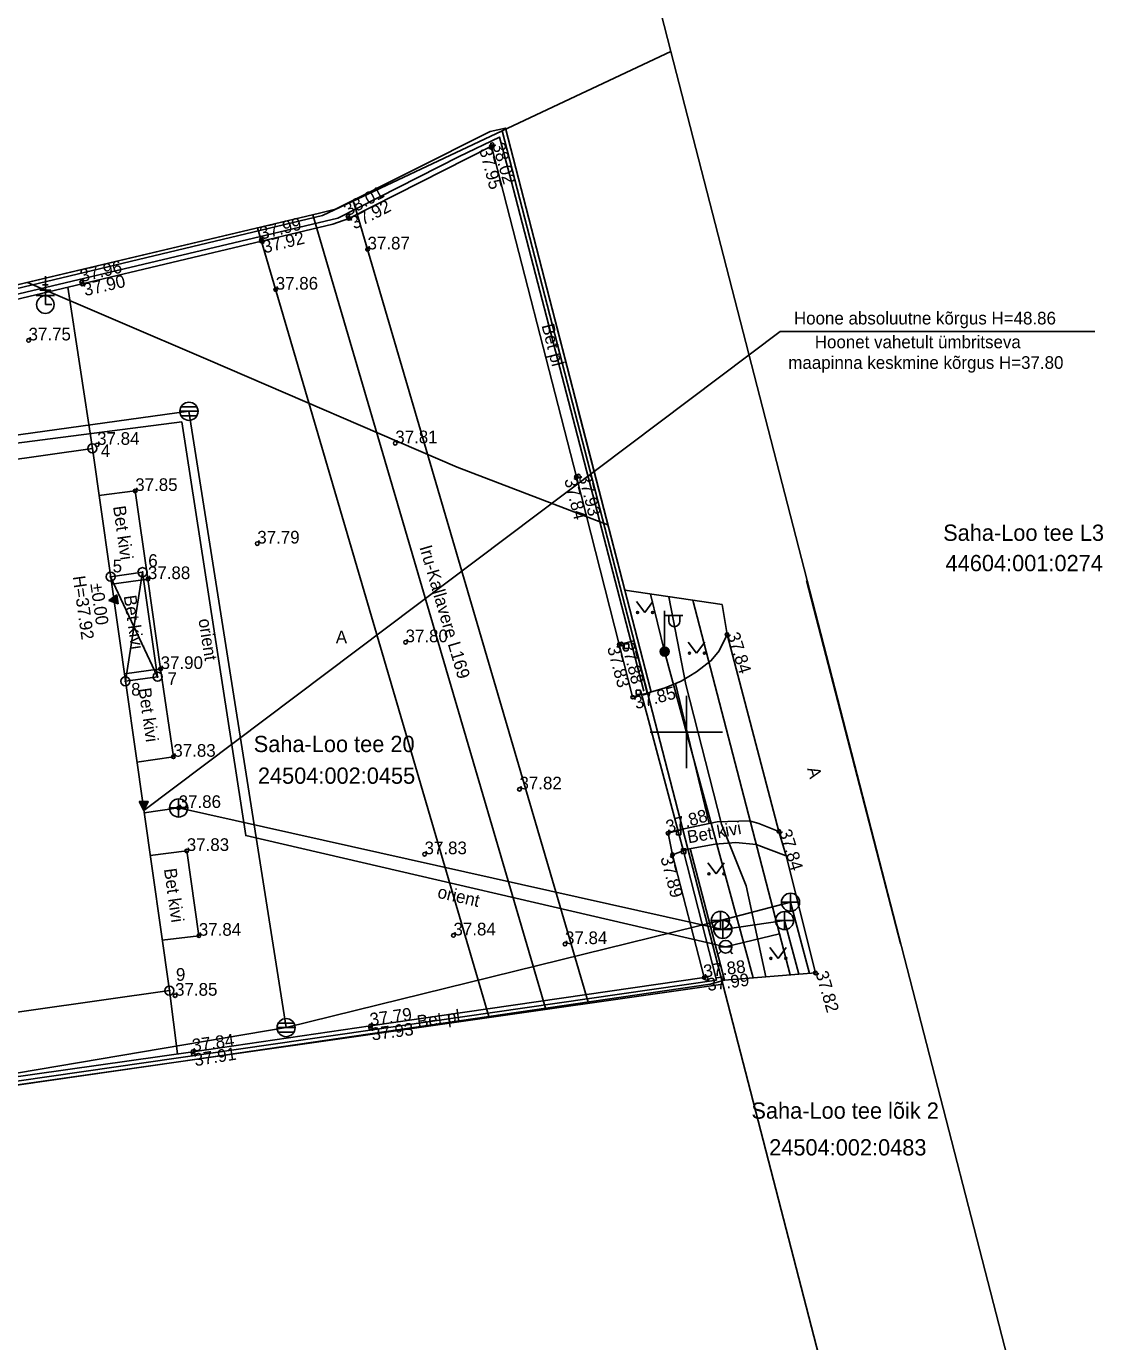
# Model space of a CAD drawing. Extents: x 551828 to 552309, y 6590593 to 6591152.
# Drawn here: x 552113.5 to 552174, y 6591016.3 to 6591089 of the extents above; entities that cross this region are included whole.
import ezdxf

# ---------------------------------------------------------------- set-up
doc = ezdxf.new("R2010")
doc.units = 0
for name, color, linetype in [('AED', 7, 'Continuous'), ('HALJASTUS', 7, 'Continuous'), ('HOONE', 7, 'Continuous'), ('HOONEDET', 7, 'Continuous'), ('KKAEV', 7, 'Continuous'), ('KOORDPUNKT', 7, 'Continuous'), ('KORGUS-EH2000', 7, 'Continuous'), ('KPOHULIIN', 7, 'Continuous'), ('KTRASS', 7, 'Continuous'), ('MOOTPIIR', 7, 'Continuous'), ('MPKAABEL', 7, 'Continuous'), ('PIIR', 7, 'Continuous'), ('POST', 7, 'Continuous'), ('PUU', 7, 'Continuous'), ('RAJATIS', 7, 'Continuous'), ('SITRASS', 7, 'Continuous'), ('SKKAEV', 7, 'Continuous'), ('SKTRASS', 7, 'Continuous'), ('TEE', 7, 'Continuous'), ('VKAEV', 7, 'Continuous'), ('VORK', 7, 'Continuous'), ('VTRASS', 7, 'Continuous')]:
    doc.layers.add(name, color=color, linetype=linetype)

msp = doc.modelspace()

# ---------------------------------------------------------------- linework, layer by layer
at = {"layer": 'AED'}
for p, q in [((552146.562, 6591054.882), (552146.562, 6591054.632)), ((552146.562, 6591054.882), (552146.812, 6591054.882)), ((552146.562, 6591054.632), (552146.812, 6591054.632)), ((552146.812, 6591054.882), (552146.812, 6591054.632)), ((552147.212, 6591052.328), (552147.212, 6591052.078)), ((552147.212, 6591052.328), (552147.462, 6591052.328)), ((552147.462, 6591052.328), (552147.462, 6591052.078)), ((552147.212, 6591052.078), (552147.462, 6591052.078)), ((552147.483, 6591052.25), (552149.566, 6591044.451)), ((552149.441, 6591044.576), (552149.441, 6591044.326)), ((552149.441, 6591044.576), (552149.691, 6591044.576)), ((552149.441, 6591044.326), (552149.691, 6591044.326)), ((552149.845, 6591043.418), (552149.566, 6591044.451)), ((552149.691, 6591044.576), (552149.691, 6591044.326)), ((552149.72, 6591043.543), (552149.72, 6591043.293)), ((552149.72, 6591043.543), (552149.97, 6591043.543)), ((552149.97, 6591043.543), (552149.97, 6591043.293)), ((552149.72, 6591043.293), (552149.97, 6591043.293))]:
    msp.add_line(p, q, dxfattribs=at)
for points in [[(552147.637, 6591052.26), (552140.304, 6591080.517), (552139.66, 6591082.912), (552137.43, 6591081.846), (552130.717, 6591078.419), (552116.026, 6591074.952), (552103.814, 6591072.044), (552061.896, 6591051.151)], [(552149.845, 6591043.418), (552151.659, 6591036.289), (552099.026, 6591028.695), (552056.657, 6591022.632), (552052.805, 6591046.621), (552057.329, 6591048.844)]]:
    msp.add_lwpolyline(points, dxfattribs=at)
msp.add_lwpolyline([(552146.282, 6591054.85), (552147.024, 6591051.953), (552147.828, 6591052.159), (552147.086, 6591055.056)], close=True, dxfattribs=at)
at = {"layer": 'HALJASTUS'}
for p, q in [((552147.238, 6591057.225), (552147.702, 6591056.618)), ((552147.702, 6591056.618), (552148.147, 6591057.225)), ((552150.1, 6591054.972), (552150.563, 6591054.366)), ((552150.563, 6591054.366), (552151.009, 6591054.972)), ((552151.184, 6591042.766), (552151.648, 6591042.159)), ((552151.648, 6591042.159), (552152.093, 6591042.766)), ((552154.609, 6591038.097), (552155.072, 6591037.49)), ((552155.072, 6591037.49), (552155.518, 6591038.097))]:
    msp.add_line(p, q, dxfattribs=at)
for centre in [(552147.301, 6591056.618), (552148.129, 6591056.618), (552150.162, 6591054.366), (552150.991, 6591054.366), (552151.247, 6591042.159), (552152.076, 6591042.159), (552154.671, 6591037.49), (552155.5, 6591037.49)]:
    msp.add_circle(centre, 0.055, dxfattribs=at)
at = {"layer": 'HOONE'}
msp.add_lwpolyline([(552071.587, 6591028.635), (552068.745, 6591048.736), (552098.36, 6591052.94), (552096.972, 6591062.824), (552117.134, 6591065.69), (552121.395, 6591035.706)], close=True, dxfattribs=at)
msp.add_lwpolyline([(552118.142, 6591058.596), (552119.91, 6591058.848), (552120.741, 6591053.064), (552118.964, 6591052.812)], dxfattribs=at)
at = {"layer": 'HOONEDET'}
for p, q in [((552118.964, 6591052.812), (552119.91, 6591058.848)), ((552118.142, 6591058.596), (552120.741, 6591053.064)), ((552118.039, 6591057.277), (552118.486, 6591057.589)), ((552118.189, 6591057.382), (552118.116, 6591057.251)), ((552118.236, 6591057.414), (552118.14, 6591057.242)), ((552118.283, 6591057.447), (552118.164, 6591057.234)), ((552118.33, 6591057.48), (552118.188, 6591057.226)), ((552118.377, 6591057.513), (552118.212, 6591057.218)), ((552118.424, 6591057.546), (552118.236, 6591057.21)), ((552118.471, 6591057.579), (552118.26, 6591057.201)), ((552118.49, 6591057.562), (552118.284, 6591057.193)), ((552118.496, 6591057.521), (552118.308, 6591057.185)), ((552118.502, 6591057.48), (552118.332, 6591057.177)), ((552118.507, 6591057.439), (552118.356, 6591057.169)), ((552118.513, 6591057.398), (552118.38, 6591057.161)), ((552118.519, 6591057.357), (552118.404, 6591057.152)), ((552118.555, 6591057.101), (552118.486, 6591057.589)), ((552118.039, 6591057.277), (552118.555, 6591057.101)), ((552118.048, 6591057.283), (552118.043, 6591057.275)), ((552118.095, 6591057.316), (552118.067, 6591057.267)), ((552118.142, 6591057.349), (552118.091, 6591057.259)), ((552118.525, 6591057.317), (552118.428, 6591057.144)), ((552118.531, 6591057.276), (552118.453, 6591057.136)), ((552118.536, 6591057.235), (552118.477, 6591057.128)), ((552118.542, 6591057.194), (552118.501, 6591057.12)), ((552118.548, 6591057.153), (552118.525, 6591057.112)), ((552118.554, 6591057.112), (552118.549, 6591057.103)), ((552119.979, 6591045.671), (552119.733, 6591046.158)), ((552120.225, 6591046.158), (552119.733, 6591046.158)), ((552119.741, 6591046.141), (552120.085, 6591045.88)), ((552119.76, 6591046.158), (552120.096, 6591045.902)), ((552119.767, 6591046.09), (552120.073, 6591045.857)), ((552119.793, 6591046.039), (552120.062, 6591045.834)), ((552119.802, 6591046.158), (552120.108, 6591045.925)), ((552119.819, 6591045.988), (552120.05, 6591045.812)), ((552119.843, 6591046.158), (552120.119, 6591045.948)), ((552119.844, 6591045.937), (552120.039, 6591045.789)), ((552119.87, 6591045.886), (552120.027, 6591045.766)), ((552119.884, 6591046.158), (552120.13, 6591045.97)), ((552119.896, 6591045.835), (552120.016, 6591045.744)), ((552119.922, 6591045.783), (552120.004, 6591045.721)), ((552119.925, 6591046.158), (552120.142, 6591045.993)), ((552119.948, 6591045.732), (552119.993, 6591045.698)), ((552119.967, 6591046.158), (552120.153, 6591046.016)), ((552119.979, 6591045.671), (552120.225, 6591046.158)), ((552120.008, 6591046.158), (552120.165, 6591046.038)), ((552120.049, 6591046.158), (552120.176, 6591046.061)), ((552120.09, 6591046.158), (552120.188, 6591046.084)), ((552120.132, 6591046.158), (552120.199, 6591046.106)), ((552120.173, 6591046.158), (552120.211, 6591046.129)), ((552120.214, 6591046.158), (552120.222, 6591046.152)), ((552119.974, 6591045.681), (552119.981, 6591045.675))]:
    msp.add_line(p, q, dxfattribs=at)
msp.add_lwpolyline([(552119.979, 6591045.671), (552155.19, 6591072.167), (552172.6, 6591072.167)], dxfattribs=at)
at = {"layer": 'KKAEV'}
for p, q in [((552121.409, 6591045.807), (552122.409, 6591045.807)), ((552121.909, 6591045.307), (552121.909, 6591046.307)), ((552155.427, 6591039.081), (552155.427, 6591040.081)), ((552152.013, 6591038.593), (552152.013, 6591039.593)), ((552154.927, 6591039.581), (552155.927, 6591039.581)), ((552151.513, 6591039.093), (552152.513, 6591039.093))]:
    msp.add_line(p, q, dxfattribs=at)
for centre in [(552121.909, 6591045.807), (552155.427, 6591039.581), (552152.013, 6591039.093)]:
    msp.add_circle(centre, 0.5, dxfattribs=at)
at = {"layer": 'KOORDPUNKT'}
for centre, radius in [((552117.134, 6591065.69), 0.25), ((552117.134, 6591065.69), 0.025), ((552117.134, 6591065.69), 0.0221), ((552117.134, 6591065.69), 0.0191), ((552117.134, 6591065.69), 0.0161), ((552117.134, 6591065.69), 0.0132), ((552117.134, 6591065.69), 0.0102), ((552117.134, 6591065.69), 0.00726), ((552117.134, 6591065.69), 0.0043), ((552118.142, 6591058.596), 0.25), ((552119.91, 6591058.848), 0.25), ((552119.91, 6591058.848), 0.025), ((552119.91, 6591058.848), 0.0221), ((552119.91, 6591058.848), 0.0191), ((552119.91, 6591058.848), 0.0161), ((552119.91, 6591058.848), 0.0132), ((552119.91, 6591058.848), 0.0102), ((552119.91, 6591058.848), 0.00726), ((552119.91, 6591058.848), 0.0043), ((552118.142, 6591058.596), 0.025), ((552118.142, 6591058.596), 0.0221), ((552118.142, 6591058.596), 0.0191), ((552118.142, 6591058.596), 0.0161), ((552118.142, 6591058.596), 0.0132), ((552118.142, 6591058.596), 0.0102), ((552118.142, 6591058.596), 0.00726), ((552118.142, 6591058.596), 0.0043), ((552118.964, 6591052.812), 0.25), ((552120.741, 6591053.064), 0.25), ((552120.741, 6591053.064), 0.025), ((552120.741, 6591053.064), 0.0221), ((552120.741, 6591053.064), 0.0191), ((552120.741, 6591053.064), 0.0161), ((552120.741, 6591053.064), 0.0132), ((552120.741, 6591053.064), 0.0102), ((552120.741, 6591053.064), 0.00726), ((552120.741, 6591053.064), 0.0043), ((552118.964, 6591052.812), 0.025), ((552118.964, 6591052.812), 0.0221), ((552118.964, 6591052.812), 0.0191), ((552118.964, 6591052.812), 0.0161), ((552118.964, 6591052.812), 0.0132), ((552118.964, 6591052.812), 0.0102), ((552118.964, 6591052.812), 0.00726), ((552118.964, 6591052.812), 0.0043), ((552121.395, 6591035.706), 0.25), ((552121.395, 6591035.706), 0.025), ((552121.395, 6591035.706), 0.0221), ((552121.395, 6591035.706), 0.0191), ((552121.395, 6591035.706), 0.0161), ((552121.395, 6591035.706), 0.0132), ((552121.395, 6591035.706), 0.0102), ((552121.395, 6591035.706), 0.00726), ((552121.395, 6591035.706), 0.0043)]:
    msp.add_circle(centre, radius, dxfattribs=at)
at = {"layer": 'KORGUS-EH2000'}
for centre in [(552139.21, 6591082.402), (552139.253, 6591082.496), (552131.28, 6591078.525), (552131.316, 6591078.414), (552126.486, 6591077.157), (552126.487, 6591077.237), (552132.358, 6591076.699), (552116.549, 6591074.89), (552116.575, 6591074.794), (552127.278, 6591074.476), (552113.605, 6591071.667), (552117.401, 6591065.892), (552133.891, 6591065.978), (552143.916, 6591064.13), (552144.029, 6591064.163), (552119.506, 6591063.34), (552126.258, 6591060.432), (552120.208, 6591058.466), (552152.244, 6591055.402), (552134.46, 6591054.973), (552146.282, 6591054.85), (552146.403, 6591054.869), (552120.911, 6591053.494), (552147.028, 6591051.936), (552121.615, 6591048.64), (552140.762, 6591046.836), (552121.909, 6591045.807), (552148.987, 6591044.41), (552155.116, 6591044.507), (552122.358, 6591043.432), (552135.511, 6591043.249), (552149.228, 6591043.224), (552123.026, 6591038.741), (552137.112, 6591038.758), (552143.28, 6591038.278), (552150.98, 6591036.429), (552151.096, 6591036.377), (552157.134, 6591036.685), (552121.712, 6591035.423), (552132.526, 6591033.639), (552132.528, 6591033.755), (552122.699, 6591032.327), (552122.714, 6591032.214)]:
    msp.add_circle(centre, 0.1, dxfattribs=at)
at = {"layer": 'KPOHULIIN'}
for p, q in [((552144.567, 6591035.072), (552131.562, 6591079.413)), ((552142.201, 6591034.727), (552129.329, 6591078.611)), ((552139.071, 6591034.269), (552126.277, 6591077.887))]:
    msp.add_line(p, q, dxfattribs=at)
at = {"layer": 'KTRASS'}
for p, q in [((552119.998, 6591045.535), (552121.909, 6591045.807)), ((552121.909, 6591045.807), (552152.013, 6591039.093)), ((552152.013, 6591039.093), (552155.427, 6591039.581)), ((552155.427, 6591039.581), (552156.209, 6591036.611))]:
    msp.add_line(p, q, dxfattribs=at)
at = {"layer": 'MOOTPIIR'}
msp.add_lwpolyline([(552103.559, 6591072.502), (552116.628, 6591075.6), (552129.697, 6591078.698), (552130.577, 6591078.919), (552139.137, 6591083.215), (552139.991, 6591083.412), (552144, 6591067.885), (552146.592, 6591057.845), (552151.974, 6591057.057), (552152.244, 6591055.402), (552155.116, 6591044.507), (552155.516, 6591043.166), (552157.134, 6591036.685), (552152.101, 6591036.283), (552151.303, 6591036.057), (552121.905, 6591031.76), (552098.767, 6591028.437)], dxfattribs=at)
at = {"layer": 'MPKAABEL'}
for points in [[(552148.01, 6591057.637), (552148.795, 6591054.459), (552153.686, 6591036.41)], [(552149.031, 6591057.488), (552149.964, 6591052.643), (552151.932, 6591044.904), (552153.302, 6591041.492), (552154.389, 6591036.466)]]:
    msp.add_lwpolyline(points, dxfattribs=at)
at = {"layer": 'PIIR'}
for points in [[(552143.71, 6591108.79), (552149.14, 6591087.65), (552174.83, 6590987.99), (552199.8, 6590891.16), (552215.43, 6590830.96), (552218.38, 6590819.63), (552233.09, 6590762.58), (552245.52, 6590714.43), (552247.96, 6590705.32), (552276.62, 6590593.49), (552283.18, 6590594.89), (552309.49, 6590600.56), (552291.06, 6590677.95), (552287.13, 6590694.59), (552278.69, 6590730.27), (552251.37, 6590840.7), (552224.32, 6590947.63), (552220.28, 6590964.73), (552176.02, 6591151.99)], [(552139.81, 6591083.25), (552152.01, 6591036.07), (552164.61, 6590987.36), (552178.47, 6590933.78), (552192.33, 6590880.2), (552205.44, 6590829.53), (552215.43, 6590830.96), (552199.8, 6590891.16), (552174.83, 6590987.99), (552149.14, 6591087.65)], [(552052.64, 6591046.67), (552056.49, 6591022.44), (552152.01, 6591036.07), (552139.81, 6591083.25), (552129.86, 6591078.57), (552103.56, 6591072.29)], [(552056.49, 6591022.44), (552064.25, 6590973.06), (552164.61, 6590987.36), (552152.01, 6591036.07)]]:
    msp.add_lwpolyline(points, close=True, dxfattribs=at)
msp.add_lwpolyline([(551994.68, 6591017.51), (552041.41, 6591041.02), (552052.64, 6591046.67), (552103.56, 6591072.29), (552129.86, 6591078.57), (552139.81, 6591083.25), (552149.14, 6591087.65), (552143.71, 6591108.79), (552138.17, 6591106.07), (552120.12, 6591097.22), (552089.7, 6591078.79), (552070.79, 6591069.29), (552053.16, 6591060.44), (552032.69, 6591050.15), (552014.5, 6591041)], dxfattribs=at)
at = {"layer": 'POST'}
for p, q in [((552148.795, 6591054.709), (552148.795, 6591056.709)), ((552148.795, 6591056.459), (552149.795, 6591056.459)), ((552149.022, 6591056.138), (552149.022, 6591056.459)), ((552149.635, 6591056.138), (552149.635, 6591056.459)), ((552148.795, 6591054.459), (552148.795, 6591054.459))]:
    msp.add_line(p, q, dxfattribs=at)
for radius in [0.25, 0.225, 0.2, 0.175, 0.15, 0.125, 0.1, 0.075, 0.05, 0.025]:
    msp.add_circle((552148.795, 6591054.459), radius, dxfattribs=at)
msp.add_arc((552149.328, 6591056.138), 0.306, 180, 0, dxfattribs=at)
at = {"layer": 'PUU'}
for p, q in [((552114.536, 6591073.647), (552114.536, 6591075.222)), ((552115.036, 6591074.147), (552114.036, 6591074.147)), ((552114.836, 6591074.447), (552114.236, 6591074.447)), ((552114.686, 6591074.747), (552114.386, 6591074.747)), ((552114.896, 6591073.647), (552114.536, 6591073.647))]:
    msp.add_line(p, q, dxfattribs=at)
at = {"layer": 'RAJATIS'}
msp.add_circle((552114.536, 6591073.647), 0.486, dxfattribs=at)
at = {"layer": 'SITRASS'}
msp.add_lwpolyline([(552113.542, 6591074.868), (552123.55, 6591070.6), (552137.32, 6591064.66), (552145.657, 6591061.464)], dxfattribs=at)
at = {"layer": 'SKKAEV'}
for p, q in [((552121.981, 6591067.745), (552122.981, 6591067.745)), ((552122.911, 6591067.995), (552122.051, 6591067.995)), ((552122.911, 6591067.495), (552122.051, 6591067.495)), ((552155.757, 6591040.093), (552155.757, 6591041.093)), ((552151.876, 6591039.084), (552151.876, 6591040.084)), ((552155.257, 6591040.593), (552156.257, 6591040.593)), ((552151.376, 6591039.584), (552152.376, 6591039.584)), ((552127.352, 6591033.656), (552128.352, 6591033.656)), ((552128.282, 6591033.906), (552127.422, 6591033.906)), ((552128.282, 6591033.406), (552127.422, 6591033.406))]:
    msp.add_line(p, q, dxfattribs=at)
for centre in [(552122.481, 6591067.745), (552155.757, 6591040.593), (552151.876, 6591039.584), (552127.852, 6591033.656)]:
    msp.add_circle(centre, 0.5, dxfattribs=at)
at = {"layer": 'SKTRASS'}
for p, q in [((552090.914, 6591063.376), (552122.481, 6591067.745)), ((552122.481, 6591067.745), (552127.852, 6591033.656)), ((552151.876, 6591039.584), (552155.757, 6591040.593)), ((552155.757, 6591040.593), (552156.816, 6591036.66)), ((552127.852, 6591033.656), (552151.876, 6591039.584)), ((552097.953, 6591028.627), (552127.852, 6591033.656))]:
    msp.add_line(p, q, dxfattribs=at)
at = {"layer": 'TEE'}
for p, q in [((552117.134, 6591065.69), (552115.783, 6591074.606)), ((552156.648, 6591058.387), (552161.845, 6591038.309)), ((552149.386, 6591052.689), (552151.256, 6591044.944)), ((552121.842, 6591032.206), (552121.395, 6591035.706))]:
    msp.add_line(p, q, dxfattribs=at)
for points in [[(552146.282, 6591054.85), (552147.086, 6591055.056), (552147.828, 6591052.159), (552148.048, 6591052.225), (552148.008, 6591052.359), (552139.991, 6591083.412), (552139.137, 6591083.215), (552130.577, 6591078.919), (552129.697, 6591078.698), (552103.559, 6591072.502), (552061.628, 6591051.575)], [(552103.896, 6591071.784), (552116.575, 6591074.794), (552126.486, 6591077.157), (552130.443, 6591078.094), (552131.316, 6591078.414), (552139.21, 6591082.402), (552143.916, 6591064.13), (552146.282, 6591054.85)], [(552117.502, 6591063.096), (552119.506, 6591063.34), (552120.208, 6591058.466), (552118.199, 6591058.191)], [(552120.208, 6591058.466), (552120.911, 6591053.494), (552118.905, 6591053.229)], [(552157.134, 6591036.685), (552155.516, 6591043.166), (552155.116, 6591044.507), (552152.244, 6591055.402), (552151.974, 6591057.057)], [(552147.828, 6591052.159), (552148.823, 6591052.458), (552149.705, 6591052.82), (552150.553, 6591053.329), (552151.373, 6591053.96), (552151.801, 6591054.504), (552152.244, 6591055.402)], [(552120.911, 6591053.494), (552121.615, 6591048.64), (552119.6, 6591048.336)], [(552057.2, 6591049.342), (552052.503, 6591047.042), (552054.752, 6591033.19), (552056.403, 6591023.066), (552056.51, 6591022.407), (552059.117, 6591022.785), (552070.742, 6591024.47), (552097.257, 6591028.201), (552097.324, 6591027.687), (552098.829, 6591027.951), (552098.767, 6591028.437), (552121.905, 6591031.76), (552151.303, 6591036.057), (552152.101, 6591036.283), (552150.21, 6591043.556)], [(552149.852, 6591044.656), (552151.702, 6591045.035), (552153.482, 6591045.092), (552154.011, 6591044.956), (552155.116, 6591044.507)], [(552149.852, 6591044.656), (552148.987, 6591044.41), (552149.228, 6591043.224), (552150.98, 6591036.429), (552132.528, 6591033.755), (552122.699, 6591032.327), (552098.285, 6591028.866)], [(552155.516, 6591043.166), (552153.863, 6591043.783), (552152.74, 6591043.899), (552151.586, 6591043.803), (552150.056, 6591043.528), (552149.228, 6591043.224)], [(552120.334, 6591043.176), (552122.358, 6591043.432), (552123.026, 6591038.741), (552120.999, 6591038.492)]]:
    msp.add_lwpolyline(points, dxfattribs=at)
at = {"layer": 'VKAEV'}
for p, q in [((552151.919, 6591037.887), (552151.779, 6591037.747)), ((552151.816, 6591038.134), (552152.516, 6591038.134)), ((552152.413, 6591037.887), (552152.553, 6591037.747))]:
    msp.add_line(p, q, dxfattribs=at)
msp.add_circle((552152.166, 6591038.134), 0.35, dxfattribs=at)
at = {"layer": 'VORK'}
for p, q in [((552150, 6591052), (552150, 6591048)), ((552148, 6591050), (552152, 6591050))]:
    msp.add_line(p, q, dxfattribs=at)
at = {"layer": 'VTRASS'}
msp.add_line((552152.166, 6591038.134), (552155.154, 6591038.852), dxfattribs=at)
for points in [[(552097.831, 6591062.946), (552098.934, 6591064.176), (552122.078, 6591067.157), (552125.621, 6591044.276), (552152.166, 6591038.134)], [(552150.351, 6591057.294), (552155.154, 6591038.852), (552155.74, 6591036.574)]]:
    msp.add_lwpolyline(points, dxfattribs=at)

# ---------------------------------------------------------------- texts
at = {"layer": 'HOONEDET'}
for s, p in [('Hoone absoluutne kõrgus H=48.86', (552155.947, 6591072.548)), ('Hoonet vahetult ümbritseva', (552157.101, 6591071.233)), ('maapinna keskmine kõrgus H=37.80', (552155.635, 6591070.094))]:
    msp.add_text(s, height=0.7, dxfattribs=at).set_placement(p)
for s, p in [('H=37.92', (552116.045, 6591058.603)), ('±0.00', (552117.022, 6591058.194))]:
    msp.add_text(s, height=0.7, rotation=278.0898, dxfattribs=at).set_placement(p)
at = {"layer": 'KOORDPUNKT'}
for s, p in [('4', (552117.607, 6591065.216)), ('5', (552118.26, 6591058.837)), ('6', (552120.227, 6591059.141)), ('7', (552121.295, 6591052.606)), ('8', (552119.28, 6591052.022)), ('9', (552121.759, 6591036.248))]:
    msp.add_text(s, height=0.7, dxfattribs=at).set_placement(p)
at = {"layer": 'KORGUS-EH2000'}
for s, rotation, p in [('37.95', 284.71435, (552138.533, 6591082.225)), ('38.02', 285.9746, (552139.253, 6591082.496)), ('38.01', 28.07902, (552131.28, 6591078.525)), ('37.92', 26.97686, (552131.634, 6591077.791)), ('37.99', 14.18851, (552126.487, 6591077.237)), ('37.92', 13.77406, (552126.653, 6591076.477)), ('37.96', 13.40771, (552116.549, 6591074.89)), ('37.90', 12.98004, (552116.732, 6591074.112)), ('37.84', 284.01176, (552143.237, 6591063.961)), ('37.93', 284.07847, (552144.029, 6591064.163)), ('37.84', 287.39927, (552152.244, 6591055.402)), ('37.83', 285.18118, (552145.606, 6591054.666)), ('37.88', 284.47422, (552146.403, 6591054.869)), ('37.85', 15.18664, (552147.212, 6591051.261)), ('37.88', 16.82995, (552148.987, 6591044.41)), ('37.84', 287.18076, (552155.116, 6591044.507)), ('37.89', 284.93272, (552148.552, 6591043.044)), ('37.88', 6.91199, (552150.98, 6591036.429)), ('37.99', 7.39723, (552151.186, 6591035.683)), ('37.82', 286.1649, (552157.134, 6591036.685)), ('37.79', 7.8724, (552132.528, 6591033.755)), ('37.93', 7.47348, (552132.617, 6591032.945)), ('37.84', 7.63735, (552122.699, 6591032.327)), ('37.91', 9.11334, (552122.825, 6591031.522))]:
    msp.add_text(s, height=0.7, rotation=rotation, dxfattribs=at).set_placement(p)
for s, p in [('37.87', (552132.358, 6591076.699)), ('37.86', (552127.278, 6591074.476)), ('37.75', (552113.605, 6591071.667)), ('37.84', (552117.401, 6591065.892)), ('37.81', (552133.891, 6591065.978)), ('37.85', (552119.506, 6591063.34)), ('37.79', (552126.258, 6591060.432)), ('37.88', (552120.208, 6591058.466)), ('37.80', (552134.46, 6591054.973)), ('37.90', (552120.911, 6591053.494)), ('37.83', (552121.615, 6591048.64)), ('37.82', (552140.762, 6591046.836)), ('37.86', (552121.909, 6591045.807)), ('37.83', (552122.358, 6591043.432)), ('37.83', (552135.511, 6591043.249)), ('37.84', (552123.026, 6591038.741)), ('37.84', (552137.112, 6591038.758)), ('37.84', (552143.28, 6591038.278)), ('37.85', (552121.712, 6591035.423))]:
    msp.add_text(s, height=0.7, dxfattribs=at).set_placement(p)
at = {"layer": 'KPOHULIIN'}
msp.add_text('Iru-Kallavere L169', height=0.7, rotation=286.34727, dxfattribs=at).set_placement((552135.224, 6591060.226))
at = {"layer": 'PIIR'}
for s, p in [('Saha-Loo tee L3', (552164.201, 6591060.581)), ('44604:001:0274', (552164.336, 6591058.902)), ('Saha-Loo tee 20', (552126.062, 6591048.897)), ('24504:002:0455', (552126.293, 6591047.145)), ('Saha-Loo tee lõik 2', (552153.594, 6591028.62)), ('24504:002:0483', (552154.577, 6591026.587))]:
    msp.add_text(s, height=0.9, dxfattribs=at).set_placement(p)
at = {"layer": 'TEE'}
for s, rotation, p in [('Bet pl', 284.44235, (552141.979, 6591072.492)), ('Bet kivi', 278.0898, (552118.278, 6591062.475)), ('Bet kivi', 278.0898, (552118.868, 6591057.531)), ('Bet kivi', 278.0898, (552119.685, 6591052.403)), ('A', 284.76763, (552156.671, 6591047.982)), ('Bet kivi', 10.18946, (552150.108, 6591043.845)), ('Bet kivi', 278.0898, (552121.093, 6591042.424)), ('Bet pl', 8.31583, (552135.148, 6591033.633))]:
    msp.add_text(s, height=0.7, rotation=rotation, dxfattribs=at).set_placement(p)
msp.add_text('A', height=0.7, dxfattribs=at).set_placement((552130.603, 6591054.914))
at = {"layer": 'VTRASS'}
for rotation, p in [(278.80218, (552123.003, 6591056.228)), (346.97303, (552136.185, 6591040.852))]:
    msp.add_text('orient', height=0.7, rotation=rotation, dxfattribs=at).set_placement(p)

doc.saveas('drawing.dxf')
